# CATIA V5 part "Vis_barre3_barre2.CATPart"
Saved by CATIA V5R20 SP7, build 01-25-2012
Part number: Vis_barre3_barre2
Bounding box of the stored display mesh (mm): x 3.5 to 8.5, y 18.193 to 20.186, z 4.769 to 6.763
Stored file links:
  J:\IFMA\IAO\système avant mef\Vis_barre3_barre2.CATPart
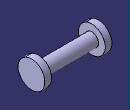
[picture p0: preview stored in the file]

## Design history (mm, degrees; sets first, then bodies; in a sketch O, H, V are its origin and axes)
Body1 (main body)
  Line1: stored without definition
  Point1 "Point.Mprim": stored without definition
  Line2 "barre_3": stored without definition
  Plane1: type Normal, Curve Line2, RefPoint Point1
  Line3 to Line5 "axe_liaison_barre2_barre3": stored without definition
  DatumCurve1 to DatumCurve3
  Line6 to Line8 "axe_liaison_barre2_barre3": stored without definition
  Sketch1 on Plane1, origin (0, 19.0247, -0.5003), H (1, 0, 0), V (0, 0.0263, 0.9997)
    point P1 (3.5, 6.2685)
    line L1 (3.5, 6.2685) -> (3.5, 7.2685)
    line L2 (3.5, 7.2685) -> (4, 7.2685)
    line L3 (4, 7.2685) -> (4, 6.7685)
    line L4 (4, 6.7685) -> (8, 6.7685)
    line L5 (8, 6.7685) -> (8, 7.2685)
    line L6 (8, 7.2685) -> (8.5, 7.2685)
    line L7 (8.5, 7.2685) -> (8.5, 6.2685)
    point P8 (8.5, 6.2685)
    reference projected line E1 (0, 6.2685) -> (20, 6.2685) from Line3
    reference projected line E2 (0, 6.2685) -> (20, 6.2685) from Line4
    reference projected line E3 (0, 6.2685) -> (20, 6.2685) from Line5
    reference projected line E4 (8, 7.2685) -> (8, 5.3797) from edge of DatumCurve1
    reference projected line E5 (4, 7.2685) -> (4, 5.2685) from edge of DatumCurve2
    reference projected line E6 (4, 7.2685) -> (4, 5.2685) from edge of DatumCurve3
    reference projected line E7 (0, 6.2685) -> (20, 6.2685) from Line6
    reference projected line E8 (0, 6.2685) -> (20, 6.2685) from Line7
    distance L4 E3 = 0.5
    distance L1 E6 = 0.5
    distance L2 E7 = 1
    distance L6 E8 = 1
    distance L7 L5 = 0.5
    vertical: L1 V, L3 V, L5 V, L7 V
    horizontal: L2 H, L4 H, L6 H
    coincidence: P1 E1, P8 E2, L5 E4, L3 E5
  Shaft1: profile Sketch1, axis Line8, angle 360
